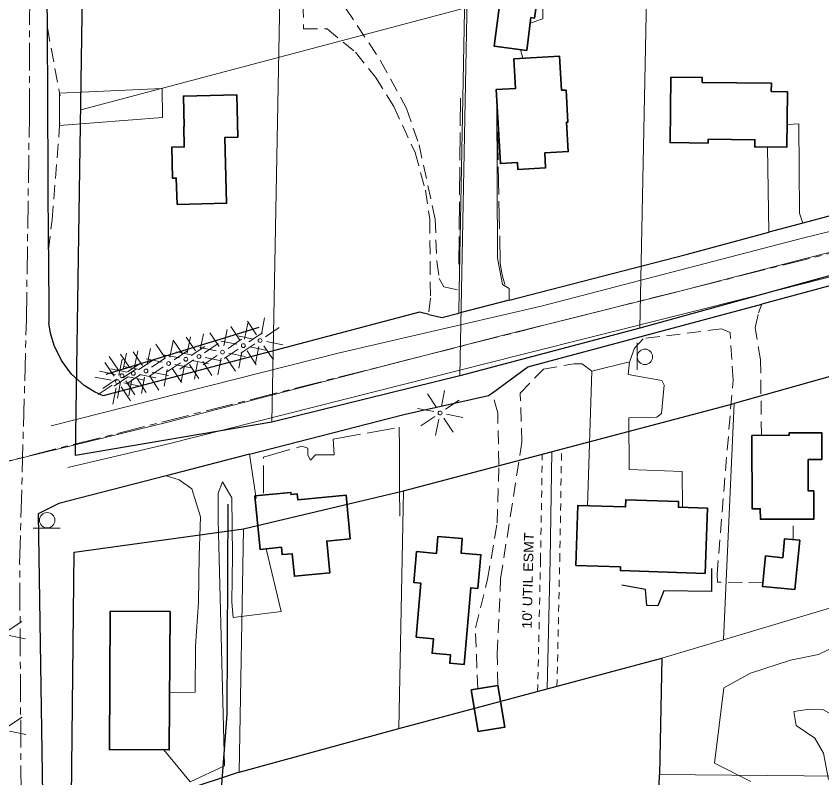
# Model space of a CAD drawing. Extents: x -861682 to -858969, y -1797841 to -1795153.
# Drawn here: x -860994.8 to -860575.4, y -1796688.4 to -1796291.8 of the extents above; entities that cross this region are included whole.
import ezdxf

# ---------------------------------------------------------------- set-up
doc = ezdxf.new("R2010")
doc.units = 0
doc.header["$LTSCALE"] = 2.4
for name, pattern in [('LONG_DASH_SHORT_DASH', [9.9, 6, -1.2, 1.5, -1.2]), ('LONG_DASHED', [7.5, 6, -1.5]), ('MEDIUM_DASHED', [4.5, 3, -1.5]), ('SHORT_DASHED', [2.7, 1.5, -1.2])]:
    doc.linetypes.add(name, pattern=pattern)
for name, color, linetype, lineweight in [('10', 7, 'Continuous', 25), ('11', 7, 'Continuous', 13), ('12', 7, 'Continuous', 35), ('14', 7, 'Continuous', 25), ('17', 7, 'Continuous', 13), ('18', 7, 'Continuous', 13), ('21', 7, 'Continuous', 13), ('30', 7, 'Continuous', 13), ('32', 7, 'LONG_DASH_SHORT_DASH', 13), ('42', 7, 'Continuous', 25), ('47', 7, 'SHORT_DASHED', 13), ('52', 7, 'LONG_DASHED', 13), ('54', 7, 'Continuous', 13)]:
    doc.layers.add(name, color=color, linetype=linetype, lineweight=lineweight)

msp = doc.modelspace()

# ---------------------------------------------------------------- linework, layer by layer
at = {"layer": '10'}
for p, q in [((-860978.567, -1796297.9), (-860979.119, -1796190.166)), ((-860977.975, -1796413.465), (-860978.567, -1796297.9)), ((-860585.314, -1796399.643), (-860602.967, -1796404.391)), ((-860977.975, -1796413.465), (-860977.781, -1796451.495)), ((-860545.1, -1796425.256), (-860606.635, -1796441.755)), ((-860738.158, -1796439.731), (-860764.405, -1796446.5)), ((-860873.273, -1796519.92), (-860916.639, -1796531.103))]:
    msp.add_line(p, q, dxfattribs=at)
for points in [[(-860526.86, -1796384.004), (-860528.934, -1796384.483), (-860585.314, -1796399.643)], [(-860738.158, -1796439.731), (-860646.097, -1796415.989), (-860602.967, -1796404.391)], [(-860746.895, -1796487.909), (-860728.402, -1796474.404), (-860606.635, -1796441.755)], [(-860780.03, -1796447.146), (-860784.776, -1796446.028), (-860949.566, -1796489.527)], [(-860780.03, -1796447.146), (-860773.174, -1796448.762), (-860764.405, -1796446.5)], [(-860949.566, -1796489.527), (-860954.087, -1796487.399), (-860959.356, -1796484.07), (-860965.921, -1796478.207), (-860971.234, -1796471.19), (-860975.096, -1796463.28), (-860976.95, -1796456.939), (-860977.781, -1796451.495)], [(-860873.273, -1796519.92), (-860793.011, -1796499.223), (-860748.888, -1796489.364), (-860746.895, -1796487.909)], [(-860916.639, -1796531.103), (-860972.545, -1796545.521), (-860983.387, -1796550.997), (-860980.82, -1796719.365)]]:
    msp.add_lwpolyline(points, dxfattribs=at)
at = {"layer": '11', "linetype": 'MEDIUM_DASHED'}
for p, q in [((-860978.567, -1796297.9), (-860972.224, -1796331.883)), ((-860971.961, -1796333.298), (-860972.224, -1796331.883)), ((-860972.074, -1796347.477), (-860972.174, -1796348.729)), ((-860590.236, -1796564.376), (-860590.332, -1796553.672))]:
    msp.add_line(p, q, dxfattribs=at)
at = {"layer": '11'}
for p, q in [((-860730.982, -1796313.817), (-860732.249, -1796309.25)), ((-860972.174, -1796348.729), (-860972.224, -1796331.883)), ((-860603.724, -1796359.986), (-860602.967, -1796404.391)), ((-860764.175, -1796434.622), (-860764.405, -1796446.5)), ((-860695.094, -1796476.632), (-860675.512, -1796471.83)), ((-860697.34, -1796546.686), (-860695.094, -1796476.632)), ((-860869.799, -1796543.002), (-860873.273, -1796519.92))]:
    msp.add_line(p, q, dxfattribs=at)
for points in [[(-860727.188, -1796295.57), (-860720.657, -1796293.294), (-860720.84, -1796272.265), (-860761.182, -1796279.706), (-860764.175, -1796434.622)], [(-860972.174, -1796348.729), (-860918.696, -1796344.647), (-860918.828, -1796329.526), (-860972.224, -1796331.883)], [(-860744.615, -1796336.745), (-860744.144, -1796417.79), (-860741.661, -1796431.474), (-860738.098, -1796433.569), (-860738.158, -1796439.731)], [(-860593.519, -1796348.212), (-860587.382, -1796347.895), (-860586.975, -1796394.442), (-860585.314, -1796399.643)], [(-860647.882, -1796547.601), (-860648.124, -1796528.872), (-860675.76, -1796527.802), (-860675.868, -1796500.88), (-860661.227, -1796500.585), (-860658.873, -1796498.686), (-860657.514, -1796484.039), (-860658.706, -1796481.446), (-860676.194, -1796478.446), (-860675.512, -1796471.83)], [(-860917.95, -1796673.813), (-860904.185, -1796690.487), (-860886.27, -1796682.149), (-860889.617, -1796554.163), (-860889.673, -1796540.23), (-860887.335, -1796534.316), (-860882.579, -1796542.563), (-860882.222, -1796572.554), (-860882.597, -1796596.88), (-860881.856, -1796604.907), (-860856.836, -1796601.737), (-860864.668, -1796569.117)], [(-860914.943, -1796644.086), (-860901.538, -1796643.716), (-860901.398, -1796619.863), (-860899.836, -1796596.949), (-860899.461, -1796572.859), (-860898.834, -1796552.547), (-860903.38, -1796537.923), (-860910.011, -1796533.227), (-860916.639, -1796531.103)]]:
    msp.add_lwpolyline(points, dxfattribs=at)
at = {"layer": '11', "linetype": 'MEDIUM_DASHED'}
for points in [[(-860836.329, -1796279.083), (-860836.275, -1796285.325), (-860845.489, -1796285.406), (-860845.14, -1796298.399), (-860832.851, -1796298.528), (-860818.095, -1796310.686), (-860807.821, -1796323.592), (-860798.236, -1796338.868), (-860787.157, -1796362.873), (-860781.787, -1796382.439), (-860779.526, -1796397.778), (-860779.169, -1796438.654), (-860780.03, -1796447.146)], [(-860823.183, -1796279.741), (-860823.257, -1796287.811), (-860805.06, -1796315.062), (-860791.61, -1796339.991), (-860785.065, -1796358.838), (-860776.693, -1796397.517), (-860775.792, -1796419.485), (-860774.533, -1796428.453), (-860772.133, -1796432.685), (-860764.175, -1796434.622)], [(-860977.975, -1796413.465), (-860976.123, -1796397.842), (-860972.174, -1796348.729)], [(-860606.834, -1796510.05), (-860607.265, -1796470.848), (-860610.166, -1796454.093), (-860608.308, -1796446.292), (-860606.635, -1796441.755)], [(-860606.139, -1796586.888), (-860629.709, -1796586.422), (-860629.962, -1796582.408), (-860621.629, -1796481.297), (-860623.145, -1796456.506), (-860627.64, -1796454.635), (-860668.475, -1796459.758), (-860672.942, -1796464.735), (-860675.512, -1796471.83)], [(-860744.07, -1796640.341), (-860744.335, -1796623.723), (-860742.603, -1796584.513), (-860731.551, -1796513.62), (-860732.362, -1796488.117), (-860720.368, -1796475.553), (-860704.556, -1796472.891), (-860700.069, -1796472.873), (-860695.094, -1796476.632)], [(-860754.481, -1796641.997), (-860755.725, -1796610.307), (-860749.45, -1796585.012), (-860744.371, -1796555.708), (-860743.548, -1796525.476), (-860744.128, -1796498.556), (-860746.895, -1796487.909)]]:
    msp.add_lwpolyline(points, dxfattribs=at)
at = {"layer": '12'}
for points in [[(-860729.021, -1796309.67), (-860726.807, -1796292.637), (-860724.892, -1796292.886), (-860723.266, -1796280.38), (-860730.783, -1796279.403), (-860731.337, -1796283.663), (-860742.625, -1796282.195), (-860745.913, -1796307.473)], [(-860744.91, -1796330.129), (-860742.683, -1796368.626), (-860733.85, -1796368.115), (-860733.648, -1796371.606), (-860719.156, -1796370.767), (-860719.603, -1796363.049), (-860707.429, -1796362.344), (-860708.312, -1796347.092), (-860707.571, -1796347.049), (-860708.542, -1796330.32), (-860710.897, -1796330.457), (-860711.929, -1796312.709), (-860735.791, -1796314.097), (-860734.893, -1796329.547)], [(-860653.993, -1796323.665), (-860654.404, -1796357.695), (-860634.567, -1796357.935), (-860634.542, -1796355.867), (-860610.251, -1796356.161), (-860610.296, -1796359.907), (-860593.662, -1796360.107), (-860593.314, -1796331.181), (-860601.708, -1796331.08), (-860601.656, -1796326.754), (-860637.631, -1796326.322), (-860637.602, -1796323.86)], [(-860910.975, -1796389.947), (-860885.225, -1796389.25), (-860886.152, -1796355.007), (-860879.384, -1796354.824), (-860879.981, -1796332.741), (-860907.713, -1796333.491), (-860907.286, -1796349.268), (-860907.55, -1796349.275), (-860907.268, -1796359.902), (-860913.829, -1796360.076), (-860913.4, -1796376.241), (-860911.45, -1796376.174)], [(-860611.83, -1796510.069), (-860611.677, -1796548.326), (-860607.426, -1796548.309), (-860607.404, -1796553.741), (-860579.537, -1796553.628), (-860579.596, -1796538.987), (-860582.43, -1796538.998), (-860582.493, -1796522.704), (-860575.41, -1796522.677), (-860575.463, -1796508.742), (-860592.47, -1796508.807), (-860592.465, -1796509.995)], [(-860870.538, -1796541.569), (-860867.828, -1796569.425), (-860856.741, -1796568.346), (-860856.368, -1796572.181), (-860851.1, -1796571.669), (-860849.957, -1796583.426), (-860831.507, -1796581.632), (-860833.115, -1796565.099), (-860820.888, -1796563.91), (-860823.087, -1796541.292), (-860848.148, -1796543.729), (-860848.455, -1796540.568), (-860851.682, -1796540.881), (-860851.791, -1796539.753)], [(-860636.102, -1796581.958), (-860680.27, -1796580.481), (-860680.207, -1796578.585), (-860703.41, -1796577.814), (-860702.37, -1796546.519), (-860677.549, -1796547.344), (-860677.426, -1796543.634), (-860649.987, -1796544.544), (-860650.086, -1796547.528), (-860634.977, -1796548.029)], [(-860786.641, -1796615.152), (-860784.156, -1796587.038), (-860787.756, -1796586.72), (-860786.331, -1796570.583), (-860776.003, -1796571.495), (-860775.229, -1796562.726), (-860762.547, -1796563.845), (-860763.209, -1796571.345), (-860752.891, -1796572.256), (-860754.437, -1796589.771), (-860758.138, -1796589.444), (-860761.667, -1796629.381), (-860769.127, -1796628.722), (-860768.739, -1796624.326), (-860778.285, -1796623.483), (-860777.62, -1796615.949)], [(-860604.73, -1796572.86), (-860606.32, -1796588.689), (-860589.493, -1796590.379), (-860586.915, -1796564.71), (-860594.78, -1796563.92), (-860595.768, -1796573.76)], [(-860945.868, -1796601.617), (-860946.287, -1796673.649), (-860915.116, -1796673.83), (-860914.697, -1796601.798)], [(-860744.031, -1796640.25), (-860740.401, -1796661.962), (-860754.302, -1796664.286), (-860757.932, -1796642.574)]]:
    msp.add_lwpolyline(points, close=True, dxfattribs=at)
at = {"layer": '14'}
msp.add_line((-860948.011, -1796478.173), (-860868.356, -1796453.847), dxfattribs=at)
for points in [[(-860953.666, -1796718.076), (-860888.328, -1796698.687), (-860884.96, -1796655.221), (-860884.454, -1796545.875)], [(-860632.807, -1796579.349), (-860632.759, -1796591.393), (-860657.558, -1796591.02), (-860660.833, -1796598.826), (-860666.501, -1796598.613), (-860667.243, -1796590.35), (-860679.533, -1796588.038)]]:
    msp.add_lwpolyline(points, dxfattribs=at)
at = {"layer": '17'}
for p, q in [((-860869.624, -1796457.795), (-860874.414, -1796450.667)), ((-860867.164, -1796457.335), (-860865.438, -1796448.935)), ((-860886.723, -1796463.413), (-860884.997, -1796455.013)), ((-860878.343, -1796460.47), (-860883.133, -1796453.342)), ((-860875.883, -1796460.01), (-860874.157, -1796451.61)), ((-860864.964, -1796458.735), (-860857.868, -1796453.995)), ((-860901.451, -1796466.107), (-860906.241, -1796458.979)), ((-860905.831, -1796467.124), (-860904.105, -1796458.724)), ((-860898.991, -1796465.647), (-860897.265, -1796457.247)), ((-860889.183, -1796463.873), (-860893.973, -1796456.745)), ((-860871.124, -1796459.995), (-860879.586, -1796458.321)), ((-860873.683, -1796461.41), (-860866.587, -1796456.67)), ((-860917.251, -1796469.789), (-860922.041, -1796462.661)), ((-860914.791, -1796469.329), (-860913.065, -1796460.929)), ((-860908.291, -1796467.584), (-860913.081, -1796460.456)), ((-860896.791, -1796467.047), (-860889.695, -1796462.307)), ((-860879.843, -1796462.67), (-860888.305, -1796460.996)), ((-860884.523, -1796464.813), (-860877.427, -1796460.073)), ((-860870.584, -1796462.495), (-860877.81, -1796467.351)), ((-860865.864, -1796463.395), (-860861.064, -1796470.609)), ((-860864.524, -1796461.255), (-860856.044, -1796462.979)), ((-860935.637, -1796474.912), (-860940.427, -1796467.784)), ((-860939.073, -1796475.685), (-860937.347, -1796467.285)), ((-860929.031, -1796473.673), (-860933.821, -1796466.545)), ((-860933.177, -1796474.452), (-860931.451, -1796466.052)), ((-860926.571, -1796473.213), (-860924.845, -1796464.813)), ((-860912.591, -1796470.729), (-860905.495, -1796465.989)), ((-860902.951, -1796468.307), (-860911.413, -1796466.633)), ((-860903.631, -1796468.524), (-860896.535, -1796463.784)), ((-860890.683, -1796466.073), (-860899.145, -1796464.399)), ((-860879.303, -1796465.17), (-860886.529, -1796470.026)), ((-860884.083, -1796467.333), (-860875.603, -1796469.057)), ((-860878.923, -1796475.13), (-860877.243, -1796466.53)), ((-860874.583, -1796466.07), (-860869.783, -1796473.284)), ((-860873.243, -1796463.93), (-860864.763, -1796465.654)), ((-860870.204, -1796472.455), (-860868.524, -1796463.855)), ((-860943.869, -1796479.238), (-860948.659, -1796472.11)), ((-860941.533, -1796476.145), (-860946.323, -1796469.017)), ((-860941.409, -1796478.778), (-860939.683, -1796470.378)), ((-860930.977, -1796475.852), (-860923.881, -1796471.112)), ((-860918.751, -1796471.989), (-860927.213, -1796470.315)), ((-860924.371, -1796474.613), (-860917.275, -1796469.873)), ((-860909.791, -1796469.784), (-860918.253, -1796468.11)), ((-860902.411, -1796470.807), (-860909.637, -1796475.663)), ((-860903.191, -1796471.044), (-860894.711, -1796472.768)), ((-860897.691, -1796471.707), (-860892.891, -1796478.921)), ((-860890.143, -1796468.573), (-860897.369, -1796473.429)), ((-860896.351, -1796469.567), (-860887.871, -1796471.291)), ((-860889.763, -1796478.533), (-860888.083, -1796469.933)), ((-860885.423, -1796469.473), (-860880.623, -1796476.687)), ((-860937.137, -1796477.112), (-860945.599, -1796475.438)), ((-860939.209, -1796480.178), (-860932.113, -1796475.438)), ((-860930.531, -1796475.873), (-860938.993, -1796474.199)), ((-860936.873, -1796477.085), (-860929.777, -1796472.345)), ((-860918.211, -1796474.489), (-860925.437, -1796479.345)), ((-860917.831, -1796484.449), (-860916.151, -1796475.849)), ((-860909.251, -1796472.284), (-860916.477, -1796477.14)), ((-860913.491, -1796475.389), (-860908.691, -1796482.603)), ((-860912.151, -1796473.249), (-860903.671, -1796474.973)), ((-860908.871, -1796482.244), (-860907.191, -1796473.644)), ((-860904.531, -1796473.184), (-860899.731, -1796480.398)), ((-860902.031, -1796480.767), (-860900.351, -1796472.167)), ((-860945.369, -1796481.438), (-860953.831, -1796479.764)), ((-860943.033, -1796478.345), (-860951.495, -1796476.671)), ((-860936.597, -1796479.612), (-860943.823, -1796484.468)), ((-860929.991, -1796478.373), (-860937.217, -1796483.229)), ((-860936.433, -1796479.605), (-860927.953, -1796481.329)), ((-860930.537, -1796478.372), (-860922.057, -1796480.096)), ((-860929.611, -1796488.333), (-860927.931, -1796479.733)), ((-860925.271, -1796479.273), (-860920.471, -1796486.487)), ((-860923.931, -1796477.133), (-860915.451, -1796478.857)), ((-860944.829, -1796483.938), (-860952.055, -1796488.794)), ((-860942.493, -1796480.845), (-860949.719, -1796485.701)), ((-860942.113, -1796490.805), (-860940.433, -1796482.205)), ((-860938.769, -1796482.698), (-860930.289, -1796484.422)), ((-860937.773, -1796481.745), (-860932.973, -1796488.959)), ((-860936.217, -1796489.572), (-860934.537, -1796480.972)), ((-860931.877, -1796480.512), (-860927.077, -1796487.726)), ((-860944.449, -1796493.898), (-860942.769, -1796485.298)), ((-860940.109, -1796484.838), (-860935.309, -1796492.052)), ((-860775.921, -1796495.539), (-860780.711, -1796488.411)), ((-860773.461, -1796495.079), (-860771.735, -1796486.679)), ((-860771.261, -1796496.479), (-860764.165, -1796491.739)), ((-860777.421, -1796497.739), (-860785.883, -1796496.065)), ((-860776.881, -1796500.239), (-860784.107, -1796505.095)), ((-860772.161, -1796501.139), (-860767.361, -1796508.353)), ((-860770.821, -1796498.999), (-860762.341, -1796500.723)), ((-860776.501, -1796510.199), (-860774.821, -1796501.599)), ((-860998.931, -1796611.691), (-860991.835, -1796606.951)), ((-860998.491, -1796614.211), (-860990.011, -1796615.935)), ((-860998.731, -1796661.52), (-860991.635, -1796656.78)), ((-860998.291, -1796664.04), (-860989.811, -1796665.764))]:
    msp.add_line(p, q, dxfattribs=at)
for centre in [(-860876.543, -1796463.37), (-860867.824, -1796460.695), (-860887.383, -1796466.773), (-860915.451, -1796472.689), (-860906.491, -1796470.484), (-860899.651, -1796469.007), (-860927.231, -1796476.573), (-860939.733, -1796479.045), (-860933.837, -1796477.812), (-860942.069, -1796482.138), (-860774.121, -1796498.439)]:
    msp.add_circle(centre, 1, dxfattribs=at)
at = {"layer": '18'}
msp.add_lwpolyline([(-860612.288, -1796690.262), (-860631.22, -1796680.655), (-860626.418, -1796641.433), (-860612.514, -1796633.82), (-860591.759, -1796627.124), (-860577.128, -1796624.232), (-860566.051, -1796618.756), (-860554.02, -1796615.401), (-860537.457, -1796623.364), (-860516.838, -1796641.466), (-860514.411, -1796657.752), (-860514.343, -1796674.755), (-860518.535, -1796689.414), (-860532.734, -1796682.15), (-860540.814, -1796669.429), (-860556.644, -1796667.84), (-860568.971, -1796656.081), (-860574.889, -1796652.798), (-860581.738, -1796652.59), (-860589.999, -1796653.804), (-860588.789, -1796661.12), (-860579.08, -1796667.693), (-860574.562, -1796675.469), (-860571.909, -1796689.156)], dxfattribs=at)
at = {"layer": '21'}
for p, q in [((-860671.524, -1796475.963), (-860671.582, -1796461.959)), ((-860971.888, -1796558.317), (-860985.892, -1796558.371))]:
    msp.add_line(p, q, dxfattribs=at)
for centre in [(-860667.493, -1796469.2), (-860978.65, -1796554.284)]:
    msp.add_circle(centre, 4, dxfattribs=at)
at = {"layer": '30'}
for p, q in [((-860670.175, -1796454.27), (-860663.246, -1796107.683)), ((-860763.871, -1796479.071), (-860757.182, -1796134.019)), ((-860861.64, -1796503.292), (-860855.359, -1796161.267)), ((-860961.174, -1796340.681), (-860367.4, -1796182.928)), ((-860795.598, -1796662.739), (-860793.193, -1796538.992)), ((-860878.673, -1796685.416), (-860876.438, -1796558.754)), ((-860658.721, -1796626.096), (-860626.627, -1796616.6)), ((-860514.881, -1796687.977), (-860659.957, -1796686.663))]:
    msp.add_line(p, q, dxfattribs=at)
for points in [[(-860536.116, -1796469.701), (-860539.529, -1796590.575), (-860626.627, -1796616.6), (-860620.958, -1796493.44)], [(-860718.3, -1796642.046), (-860716.82, -1796574.948), (-860715.899, -1796518.55)]]:
    msp.add_lwpolyline(points, dxfattribs=at)
at = {"layer": '32'}
for points in [[(-861016.908, -1797697.112), (-861016.908, -1797629.868), (-861015.071, -1797572.938), (-861015.071, -1797447.139), (-861012.317, -1797374.599), (-861007.726, -1797281.857), (-861003.087, -1797084.148), (-860992.207, -1796696.344), (-860992.984, -1796576.661), (-860989.487, -1796449.983), (-860987.933, -1796343.901), (-860987.544, -1796199.737), (-860984.047, -1796080.831), (-860987.933, -1795887.705), (-860991.735, -1795769.455)], [(-861651.105, -1796687.844), (-861333.558, -1796608.31), (-860734.009, -1796456.297), (-860402.78, -1796372.876), (-860279.286, -1796339.345), (-860213.04, -1796323.806), (-860166.423, -1796315.627), (-860126.348, -1796310.72), (-860089.545, -1796308.267), (-860056.831, -1796312.356), (-859995.492, -1796331.984), (-859827.834, -1796395.777), (-859764.042, -1796414.588), (-859688.8, -1796435.852), (-859629.915, -1796444.03), (-859562.034, -1796449.756), (-859471.253, -1796448.938), (-859395.193, -1796443.213), (-859240.62, -1796421.131), (-859002.083, -1796383.657)]]:
    msp.add_lwpolyline(points, dxfattribs=at)
at = {"layer": '42'}
for p, q in [((-860570.941, -1796426.918), (-860670.175, -1796454.27)), ((-860670.175, -1796454.27), (-860763.871, -1796479.071)), ((-860536.116, -1796469.701), (-860620.958, -1796493.44)), ((-860763.871, -1796479.071), (-860861.64, -1796503.292)), ((-860793.193, -1796538.992), (-860620.958, -1796493.44)), ((-860876.438, -1796558.754), (-860793.193, -1796538.992)), ((-860795.598, -1796662.739), (-860658.721, -1796626.096)), ((-860658.721, -1796626.096), (-860659.957, -1796686.663)), ((-860878.673, -1796685.416), (-860795.598, -1796662.739)), ((-860661.564, -1796767.058), (-860659.957, -1796686.663))]:
    msp.add_line(p, q, dxfattribs=at)
for points in [[(-860861.64, -1796503.292), (-860963.86, -1796520.607), (-860958.897, -1796188.151), (-860855.359, -1796161.267)], [(-860878.673, -1796685.416), (-860966.096, -1796714.466), (-860964.664, -1796570.952), (-860876.438, -1796558.754)]]:
    msp.add_lwpolyline(points, dxfattribs=at)
at = {"layer": '47'}
for points in [[(-860713.269, -1796640.699), (-860711.821, -1796575.044), (-860710.877, -1796517.221)], [(-860723.331, -1796643.393), (-860721.819, -1796574.852), (-860720.921, -1796519.878)]]:
    msp.add_lwpolyline(points, dxfattribs=at)
at = {"layer": '52'}
msp.add_line((-860764.309, -1796420.891), (-860763.551, -1796333.129), dxfattribs=at)
for points in [[(-860740.494, -1796431.58), (-860741.847, -1796426.574), (-860742.795, -1796420.62), (-860744.401, -1796342.081)], [(-860866.057, -1796540.136), (-860866.132, -1796521.479), (-860846.081, -1796515.731), (-860843.007, -1796516.663), (-860842.992, -1796520.442), (-860841.565, -1796523.034), (-860838.978, -1796520.189), (-860829.296, -1796520.151), (-860829.8, -1796512.123), (-860795.346, -1796505.845), (-860795.302, -1796516.708), (-860795.268, -1796525.21), (-860795.218, -1796537.726), (-860795.158, -1796552.604)]]:
    msp.add_lwpolyline(points, dxfattribs=at)
at = {"layer": '54'}
for points in [[(-860172.631, -1796317.253), (-860204.018, -1796322.811), (-860236.107, -1796330.26), (-860268.193, -1796338.182), (-860308.776, -1796347.556), (-860380.023, -1796366.026), (-860439.712, -1796381.144), (-860499.871, -1796396.736), (-860533.844, -1796405.374), (-860583.86, -1796418.091), (-860653.219, -1796436.08), (-860743.108, -1796458.404), (-860803.739, -1796473.997), (-860915.799, -1796503.257), (-861038.012, -1796533.031), (-861123.178, -1796555.335), (-861206.46, -1796575.979), (-861319.702, -1796605.009), (-861464.557, -1796642.43), (-861630.889, -1796683.009), (-861651.109, -1796688.034)], [(-860357.714, -1796346.597), (-860443.038, -1796371.209), (-860509.283, -1796388.801), (-860584.737, -1796407.182), (-860721.476, -1796442.876), (-860826.415, -1796467.186), (-860976.604, -1796505.123)], [(-860326.19, -1796362.976), (-860392.479, -1796381.19), (-860489.207, -1796405.903), (-860542.286, -1796420.286), (-860608.581, -1796437.082), (-860732.913, -1796468.281), (-860916.226, -1796514.595), (-860967.897, -1796526.846)]]:
    msp.add_lwpolyline(points, dxfattribs=at)

# ---------------------------------------------------------------- texts
at = {"layer": '47', "width": 1.1}
msp.add_text("10' UTIL ESMT", height=5, rotation=88.739, dxfattribs=at).set_placement((-860726.443, -1796610.731))

doc.saveas('drawing.dxf')
